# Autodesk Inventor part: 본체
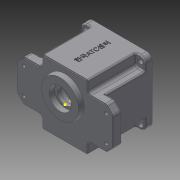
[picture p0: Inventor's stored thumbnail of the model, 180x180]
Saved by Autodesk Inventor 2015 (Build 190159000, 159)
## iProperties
Created: 2016-02
Part Number: 본체
Material: Generic
Document SubType Name: Modeling
Designer: Administrator
Density: 1 g/cm^3
Appearance: Default
Author: Administrator
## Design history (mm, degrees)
sketch "Sketch1"
  geometry: L1 (47, -47)-(-47, -47); L2 (-47, -47)-(-47, 47); L3 (-47, 47)-(47, 47); L4 (47, 47)-(47, -47); L5 (47, -47)-(-47, 47); L6 (-47, -47)-(47, 47); 1 further point
  constraints: 12 end point, 2 midpoint, 2 parallel, 1 horizontal, 1 perpendicular
  dimensions: "d0" = 94 distance of L2.end L3.end; "d1" = 94 distance of L1.end L2.end
extrude "Extrusion1" new body sketch "Sketch1" distance "d2" = 10; taper "d3" = 0 deg
workplane "Work Plane1"
sketch "Sketch2"
  geometry: L1 (33, -47)-(-33, -47); L2 (-33, 47)-(33, 47); L3 (33, -47)-(-33, 47); L4 (-33, -47)-(33, 47); L5 (-70, 30)-(-70, -30); L6 (70, -30)-(70, 30); L7 (70, 30)-(33, 30); L8 (-33, 30)-(-70, 30); L9 (-70, -30)-(-33, -30); L10 (33, -30)-(70, -30); L11 (33, 47)-(33, 30); L12 (33, -30)-(33, -47); L13 (-33, -47)-(-33, -30); L14 (-33, 30)-(-33, 47); 1 further point
  constraints: 28 end point, 10 parallel, 4 perpendicular, 3 horizontal, 2 midpoint
  dimensions: "d5" = 94 distance of L1.end L2.start; "d6" = 66 distance of L2.start L2.end; "d8" = 140 distance of L6.end L5.start; "d9" = 70 distance from line of L5 point (0, 0); "d10" = 60 distance of L5.start L5.end
extrude "Extrusion2" join sketch "Sketch2" distance "d12" = 13; taper "d13" = 0 deg
workplane "Work Plane2"
sketch "Sketch3"
  geometry: L1 (47, -47)-(-47, -47) reference; L2 (-47, -47)-(-47, 47) reference; L3 (-47, 47)-(47, 47) reference; L4 (47, 47)-(47, -47) reference; L5 (-33, 30)-(-33, 47) reference; L6 (-47, 47)-(-33, 47); L7 (-33, 47)-(-33, 30); L8 (-33, 30)-(-47, 30); L9 (-47, 30)-(-47, 47); L10 (-47, -47)-(-33, -47); L11 (-33, -47)-(-33, -30); L12 (-33, -30)-(-47, -30); L13 (-47, -30)-(-47, -47); L14 (47, -47)-(33, -47); L15 (33, -47)-(33, -30); L16 (33, -30)-(47, -30); L17 (47, -30)-(47, -47); L18 (47, 47)-(33, 47); L19 (33, 47)-(33, 30); L20 (33, 30)-(47, 30); L21 (47, 30)-(47, 47); 1 further point
  constraints: 32 end point, 8 parallel, 4 horizontal, 4 perpendicular
extrude "Extrusion3" join sketch "Sketch3" stored distance "d15" = 10; taper "d16" = 0 deg
sketch "Sketch4"
  geometry: L1 (47, 47)-(33, 47); L2 (33, 47)-(33, 30); L3 (33, 30)-(47, 30); L4 (47, 30)-(47, 47); L5 (47, -47)-(33, -47); L6 (33, -47)-(33, -30); L7 (33, -30)-(47, -30); L8 (47, -30)-(47, -47); L9 (-47, -47)-(-33, -47); L10 (-33, -47)-(-33, -30); L11 (-33, -30)-(-47, -30); L12 (-47, -30)-(-47, -47); L13 (-47, 47)-(-33, 47); L14 (-33, 47)-(-33, 30); L15 (-33, 30)-(-47, 30); L16 (-47, 30)-(-47, 47); 1 further point
  constraints: 32 end point, 8 parallel, 4 horizontal, 4 perpendicular
extrude "Extrusion4" cut sketch "Sketch4" distance "d17" = 60; taper "d18" = 0 deg
fillet "Fillet1" dims "d19" = 8
sketch "Sketch5"
  geometry: C1 r 43 at (0, 0); 1 further point
  constraints: 1 centre point, 1 coincident
  dimensions: "d20" = 43 radius of C1
extrude "Extrusion5" cut sketch "Sketch5" distance "d21" = 9; taper "d22" = 0 deg
sketch "Sketch6"
  geometry: C1 r 40 at (0, 0); 1 further point
  constraints: 1 centre point, 1 coincident
  dimensions: "d81" = 40 radius of C1
extrude "Extrusion6" cut sketch "Sketch6" distance "d24" = 62; taper "d25" = 0 deg
sketch "Sketch8"
  geometry: C1 r 28 at (0, 11); 1 further point
  constraints: 1 centre point, 1 vertical alignment
  dimensions: "d32" = 28 radius of C1; "d33" = 11 distance of point (0, 0) C1.centre
extrude "Extrusion8" join sketch "Sketch8" distance "d34" = 7; taper "d35" = -10 deg
sketch "Sketch9"
  geometry: 1 further point
sketch "Sketch10"
  geometry: C1 r 21 at (0, -11); 1 further point
  constraints: 1 centre point, 1 vertical alignment
  dimensions: "d36" = 21 radius of C1; "d37" = 11 distance of point (0, 0) C1.centre
extrude "Extrusion9" join sketch "Sketch10" distance "d38" = 7; taper "d39" = 0 deg
sketch "Sketch12"
  geometry: C1 r 16 at (0, 0); C2 r 28 at (0, 0) reference; 1 further point
  constraints: 1 centre point, 1 concentric
  dimensions: "d43" = 16 radius of C1
extrude "Extrusion11" cut sketch "Sketch12" distance "d44" = 8; taper "d45" = 0 deg
sketch "Sketch13"
  geometry: C1 r 15 at (0, 20); 1 further point
  constraints: 1 centre point, 1 vertical alignment
  dimensions: "d46" = 15 radius of C1; "d47" = 20 distance of point (0, 0) C1.centre
extrude "Extrusion12" join sketch "Sketch13" distance "d48" = 7; taper "d49" = 0 deg
sketch "Sketch14"
  geometry: C1 r 11 at (0, 20); A1 r 15 centre (0, 20) between (8.978, 7.984) and (-8.978, 7.984) reference; 1 further point
  constraints: 1 centre point, 1 coincident, 1 vertical alignment
  dimensions: "d50" = 11 radius of C1
extrude "Extrusion13" cut sketch "Sketch14" distance "d51" = 7; taper "d52" = 0 deg
sketch "Sketch15"
  geometry: C1 r 9.5 at (0, 0); C2 r 11 at (0, 0) reference; 1 further point
  constraints: 1 centre point, 1 concentric
  dimensions: "d53" = 9.5 radius of C1
extrude "Extrusion14" cut sketch "Sketch15" distance "d54" = 1; taper "d55" = 0 deg
chamfer "Chamfer1" distance "d56" = 10; stored, may be unused: second distance "d57" = 2, angle "d58" = 45 deg
fillet "Fillet2" dims "d62" = 2
fillet "Fillet4" dims "d64" = 2
fillet "Fillet5" dims "d65" = 3
sketch "Sketch17"
  geometry: A1 r 40 centre (0, 0) between (40, 0) and (-40, 0) reference; A2 r 3.5 centre (35.95, -6.312) between (39.397, -6.918) and (37.84, -3.367); A3 r 3.5 centre (-35.95, -6.312) between (-37.84, -3.367) and (-39.397, -6.918); A4 r 3.5 centre (-35.95, 6.312) between (-39.397, 6.918) and (-37.84, 3.367); A5 r 3.5 centre (35.95, 6.312) between (37.84, 3.367) and (39.397, 6.918); A6 r 4 centre (40, 0) between (37.84, 3.367) and (37.84, -3.367); A7 r 4 centre (-40, 0) between (-37.84, -3.367) and (-37.84, 3.367); 2 further points
  constraints: 18 point on circle, 6 centre point, 4 tangent, 3 horizontal alignment, 1 coincident, 2 other
  dimensions: "d84" = 3.5 radius of A3; "d85" = 3.5 radius of A4; "d86" = 3.5 radius of A5; "d87" = 3.5 radius of A2
extrude "Extrusion16" join sketch "Sketch17" stored distance "d88" = 1; taper "d89" = 0 deg
fillet "Fillet6" dims "d90" = 3
sketch "Sketch18"
  geometry: L1 (40, 40)-(-40, 40); L2 (-40, 40)-(-40, -40); L3 (-40, -40)-(40, -40); L4 (40, -40)-(40, 40); L5 (40, 40)-(-40, -40); L6 (-40, 40)-(40, -40); 5 further points
  constraints: 12 end point, 4 coincident, 2 midpoint, 2 parallel, 1 horizontal, 1 perpendicular
  dimensions: "d91" = 80 distance of L3.end L2.end; "d92" = 80 distance of L2.end L1.end
hole "Hole1" sketch "Sketch18" at (40, -40), (-40, -40), (-40, 40), (40, 40) diameter "d93" = 7; stored, may be unused: countersink angle "d97" = 90 deg, drill point angle "d99" = 118 deg; dims "d94" = 6, "d95" = 4, "d96" = 2, "d98" = 8
fillet "Fillet7" dims "d100" = 3
sketch "Sketch19"
  geometry: L1 (-60, -19)-(60, -19); L2 (60, -19)-(60, 19); L3 (60, 19)-(-60, 19); L4 (-60, 19)-(-60, -19); L5 (-60, -19)-(60, 19); L6 (60, -19)-(-60, 19); 5 further points
  constraints: 12 end point, 4 coincident, 2 midpoint, 2 parallel, 1 horizontal, 1 perpendicular
  dimensions: "d101" = 120 distance of L3.end L2.end; "d102" = 38 distance of L2.end L1.end
sketch "Sketch20"
  geometry: L1 (-60, 19)-(60, 19) reference; L2 (-60, -19)-(-60, 19) reference; L3 (60, -19)-(-60, -19) reference; L4 (60, 19)-(60, -19) reference; 5 further points
  constraints: 4 coincident
hole "Hole2" sketch "Sketch20" at (-60, 19), (60, 19), (60, -19), (-60, -19) diameter "d103" = 5; stored, may be unused: countersink angle "d107" = 90 deg, drill point angle "d109" = 118 deg; dims "d104" = 6, "d105" = 9, "d106" = 4, "d108" = 8
chamfer "Chamfer3" distance "d115" = 1; stored, may be unused: second distance "d116" = 2, angle "d117" = 45 deg
fillet "Fillet8" dims "d121" = 0.3
fillet "Fillet9" dims "d122" = 1
sketch "Sketch25"
  geometry: L1 (0, 0)-(78, 0) reference; L2 (39, 16)-(39, -96) reference; 2 further points
  constraints: 1 midpoint, 1 other
  dimensions: "d123" = 40 distance from line of L1 point (39, -40)
emboss "Emboss1" sketch "Sketch25" dims "d5" = 94, "d6" = 66, "d8" = 140, "d9" = 70, "d10" = 60, "d124" = 0.5, "d125" = 0
fillet "Fillet12" dims "d128" = 5
fillet "Fillet13" dims "d129" = 5
fillet "Fillet14" dims "d130" = 2
fillet "Fillet15" dims "d131" = 2
sketch "Sketch26"
  geometry: C1 r 17.5 at (0, -11); A1 r 21 centre (0, -11) between (-12.163, 6.119) and (12.163, 6.119) reference; 1 further point
  constraints: 1 centre point, 1 concentric
  dimensions: "d132" = 17.5 radius of C1
extrude "Extrusion20" cut sketch "Sketch26" distance "d133" = 10; taper "d134" = 0 deg
sketch "Sketch27"
  geometry: C1 r 12.5 at (0, 0); C2 r 17.5 at (0, 0) reference; 1 further point
  constraints: 1 centre point, 1 concentric
  dimensions: "d135" = 12.5 radius of C1
extrude "Extrusion21" cut sketch "Sketch27" distance "d136" = 5; taper "d137" = 0 deg
fillet "Fillet16" dims "d138" = 0.3
chamfer "Chamfer4" distance "d139" = 1; stored, may be unused: second distance "d140" = 2, angle "d141" = 45 deg
sketch "Sketch28"
  geometry: 1 further point
fillet "Fillet19" dims "d145" = 2
sketch "Sketch30"
  geometry: L1 (-33, 45)-(-33, 35) reference; L2 (-38, 30)-(-57.929, 30) reference; L3 (-68.536, 21.464)-(-61.464, 28.536) reference; L4 (-70, 17.929)-(-70, -17.929) reference; L5 (-61.464, -28.536)-(-68.536, -21.464) reference; L6 (-57.929, -30)-(-38, -30) reference; L7 (-33, -35)-(-33, -45) reference; L8 (-31, -47)-(31, -47) reference; L9 (33, -45)-(33, -35) reference; L10 (38, -30)-(57.929, -30) reference; L11 (68.536, -21.464)-(61.464, -28.536) reference; L12 (70, -17.929)-(70, 17.929) reference; L13 (61.464, 28.536)-(68.536, 21.464) reference; L14 (57.929, 30)-(38, 30) reference; L15 (33, 35)-(33, 45) reference; L16 (31, 47)-(-31, 47) reference; L17 (-32, 45)-(-32, 35); L18 (-38, 29)-(-57.929, 29); L19 (-60.757, 27.828)-(-67.828, 20.757); L20 (-69, 17.929)-(-69, -17.929); L21 (-67.828, -20.757)-(-60.757, -27.828); L22 (-57.929, -29)-(-38, -29); L23 (-32, -35)-(-32, -45); L24 (-31, -46)-(31, -46); L25 (32, -45)-(32, -35); L26 (38, -29)-(57.929, -29); L27 (60.757, -27.828)-(67.828, -20.757); L28 (69, -17.929)-(69, 17.929); L29 (67.828, 20.757)-(60.757, 27.828); L30 (57.929, 29)-(38, 29); L31 (32, 35)-(32, 45); L32 (31, 46)-(-31, 46); C1 r 2.5 at (60, 19) reference; C2 r 2.5 at (-60, -19) reference; C3 r 2.5 at (60, -19) reference; C4 r 2.5 at (-60, 19) reference; C5 r 28 at (0, 11) reference; A1 r 2 centre (-31, 45) between (-31, 47) and (-33, 45) reference; A2 r 5 centre (-38, 35) between (-38, 30) and (-33, 35) reference; A3 r 5 centre (-57.929, 25) between (-57.929, 30) and (-61.464, 28.536) reference; A4 r 5 centre (-65, 17.929) between (-68.536, 21.464) and (-70, 17.929) reference; A5 r 5 centre (-65, -17.929) between (-70, -17.929) and (-68.536, -21.464) reference; A6 r 5 centre (-57.929, -25) between (-61.464, -28.536) and (-57.929, -30) reference; A7 r 5 centre (-38, -35) between (-33, -35) and (-38, -30) reference; A8 r 2 centre (-31, -45) between (-33, -45) and (-31, -47) reference; A9 r 2 centre (31, -45) between (31, -47) and (33, -45) reference; A10 r 5 centre (38, -35) between (38, -30) and (33, -35) reference; A11 r 5 centre (57.929, -25) between (57.929, -30) and (61.464, -28.536) reference; A12 r 5 centre (65, -17.929) between (68.536, -21.464) and (70, -17.929) reference; A13 r 5 centre (65, 17.929) between (70, 17.929) and (68.536, 21.464) reference; A14 r 5 centre (57.929, 25) between (61.464, 28.536) and (57.929, 30) reference; A15 r 5 centre (38, 35) between (33, 35) and (38, 30) reference; A16 r 2 centre (31, 45) between (33, 45) and (31, 47) reference; A17 r 1 centre (-31, 45) between (-31, 46) and (-32, 45); A18 r 6 centre (-38, 35) between (-38, 29) and (-32, 35); A19 r 4 centre (-57.929, 25) between (-57.929, 29) and (-60.757, 27.828); A20 r 4 centre (-65, 17.929) between (-67.828, 20.757) and (-69, 17.929); A21 r 4 centre (-65, -17.929) between (-69, -17.929) and (-67.828, -20.757); A22 r 4 centre (-57.929, -25) between (-60.757, -27.828) and (-57.929, -29); A23 r 6 centre (-38, -35) between (-32, -35) and (-38, -29); A24 r 1 centre (-31, -45) between (-32, -45) and (-31, -46); A25 r 1 centre (31, -45) between (31, -46) and (32, -45); A26 r 6 centre (38, -35) between (38, -29) and (32, -35); A27 r 4 centre (57.929, -25) between (57.929, -29) and (60.757, -27.828); A28 r 4 centre (65, -17.929) between (67.828, -20.757) and (69, -17.929); A29 r 4 centre (65, 17.929) between (69, 17.929) and (67.828, 20.757); A30 r 4 centre (57.929, 25) between (60.757, 27.828) and (57.929, 29); A31 r 6 centre (38, 35) between (32, 35) and (38, 29); A32 r 1 centre (31, 45) between (32, 45) and (31, 46); 1 further point
  constraints: 32 end point, 32 point on circle, 16 centre point, 31 other
  dimensions: "d146" = 1 distance between parallel lines of L16 L32
extrude "Extrusion22" cut sketch "Sketch30" distance "d147" = 1; taper "d148" = 0 deg
sketch "Sketch31"
  geometry: A1 r 40 centre (0, 0) between (-39.397, -6.918) and (39.397, -6.918) reference; 3 further points
  constraints: 2 horizontal alignment, 2 point on circle
hole "Hole3" sketch "Sketch31" at (-40, 0), (40, 0) diameter "d149" = 3.242; stored, may be unused: countersink angle "d153" = 90 deg, drill point angle "d155" = 118 deg; dims "d150" = 8, "d151" = 4, "d152" = 2, "d154" = 9
body "Solid1"
node "Projected Loop1"
node "Projected Loop4"
other parameters: "d82" = 4, "d83" = 4
